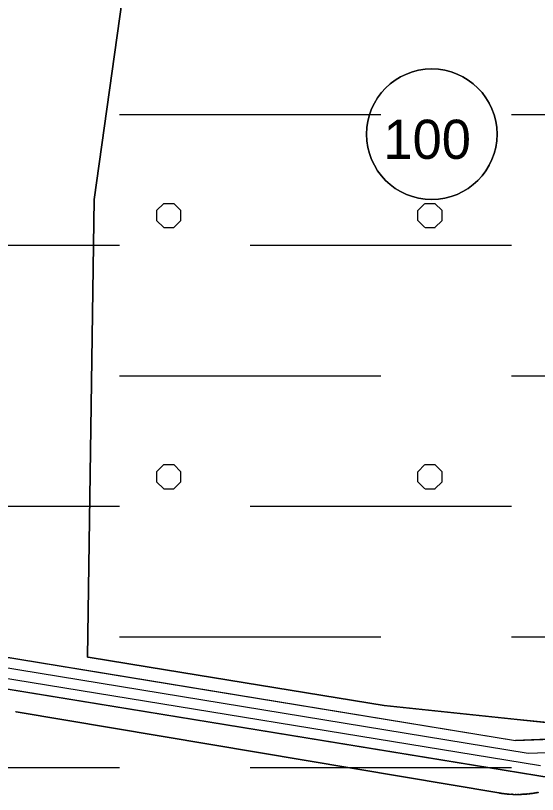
# Model space of a CAD drawing. Extents: x 409341 to 428634, y 4447481 to 4463281.
# Drawn here: x 419692.6 to 419892.4, y 4458246.6 to 4458544.8 of the extents above; entities that cross this region are included whole.
import ezdxf

# ---------------------------------------------------------------- set-up
doc = ezdxf.new("R2010")
doc.units = 0
for name, color, linetype in [('ADAKENARI', 7, 'Continuous'), ('KALDIRIM', 7, 'Continuous'), ('PL_KA_TARIM_ALANI', 7, 'Continuous'), ('PL_KON_ONE_100', 7, 'Continuous'), ('SM_DAIRE', 7, 'Continuous'), ('SM_TAKS', 7, 'Continuous'), ('SN_TR_TASKIN', 7, 'Continuous'), ('TR_AZGELISME', 7, 'Continuous'), ('TR_TARIMALANI', 7, 'Continuous')]:
    doc.layers.add(name, color=color, linetype=linetype)

msp = doc.modelspace()

# ---------------------------------------------------------------- linework, layer by layer
at = {"layer": 'ADAKENARI'}
for p, q in [((419722.68, 4458474.32), (419720.19, 4458299.14)), ((419673.34, 4458301.74), (419884.01, 4458267.29)), ((419671.41, 4458289.89), (419898.39, 4458252.78)), ((419833.71, 4458280.58), (419884.64, 4458275.31)), ((419884.64, 4458275.31), (419906.29, 4458273.07)), ((419955.41, 4458269.77), (419884.01, 4458267.29))]:
    msp.add_line(p, q, dxfattribs=at)
for points in [[(419783, 4458743.98), (419782.81, 4458726.4), (419748.11, 4458655.62), (419722.68, 4458474.32)], [(419720.19, 4458299.14), (419721.17, 4458298.98), (419750.03, 4458294.26), (419833.71, 4458280.58)]]:
    msp.add_lwpolyline(points, dxfattribs=at)
at = {"layer": 'KALDIRIM'}
for p, q in [((419672.7, 4458297.79), (419888.8, 4458262.45)), ((419672.05, 4458293.84), (419893.6, 4458257.62)), ((419888.8, 4458262.45), (419955.19, 4458264.76))]:
    msp.add_line(p, q, dxfattribs=at)
at = {"layer": 'PL_KA_TARIM_ALANI'}
for p, q in [((419692.64, 4458278.3), (419692.55, 4458278.32)), ((419878.14, 4458247.09), (419878.03, 4458247.11)), ((419891.85, 4458247.23), (419891.74, 4458247.22)), ((419881.06, 4458246.75), (419880.95, 4458246.75)), ((419881.28, 4458246.73), (419881.17, 4458246.74)), ((419882.48, 4458246.65), (419882.37, 4458246.66)), ((419882.8, 4458246.64), (419882.69, 4458246.64)), ((419883.24, 4458246.62), (419883.13, 4458246.62)), ((419883.79, 4458246.61), (419883.68, 4458246.61)), ((419886.85, 4458246.66), (419886.75, 4458246.65)), ((419888.49, 4458246.78), (419888.38, 4458246.77)), ((419888.82, 4458246.81), (419888.71, 4458246.8)), ((419889.36, 4458246.87), (419889.25, 4458246.86))]:
    msp.add_line(p, q, dxfattribs=at)
for points in [[(419673.34, 4458301.74), (419884.01, 4458267.29), (419932.9, 4458268.99), (419933.38, 4458274.01), (419913.55, 4458273.32), (419906.29, 4458273.07), (419884.64, 4458275.31), (419833.71, 4458280.58), (419750.03, 4458294.26), (419721.17, 4458298.98), (419720.19, 4458299.14), (419722.68, 4458474.32), (419748.11, 4458655.62), (419782.81, 4458726.4), (419783, 4458743.98), (419717.61, 4458711.06)], [(419930.98, 4458248.91), (419931.46, 4458253.93), (419898.39, 4458252.78), (419671.41, 4458289.89)], [(419692.55, 4458278.32), (419692.64, 4458278.3), (419692.73, 4458278.29), (419692.82, 4458278.27), (419692.92, 4458278.26), (419692.92, 4458278.26), (419877.6, 4458247.18), (419877.6, 4458247.18), (419877.71, 4458247.16), (419877.81, 4458247.15), (419877.92, 4458247.13), (419878.03, 4458247.11), (419878.14, 4458247.09), (419878.24, 4458247.08), (419878.35, 4458247.06), (419878.46, 4458247.05), (419878.57, 4458247.03), (419878.67, 4458247.01), (419878.78, 4458247), (419878.89, 4458246.98), (419879, 4458246.97), (419879.11, 4458246.96), (419879.21, 4458246.94), (419879.32, 4458246.93), (419879.43, 4458246.91), (419879.54, 4458246.9), (419879.65, 4458246.89), (419879.75, 4458246.88), (419879.86, 4458246.86), (419879.97, 4458246.85), (419880.08, 4458246.84), (419880.19, 4458246.83), (419880.3, 4458246.82), (419880.41, 4458246.81), (419880.51, 4458246.79), (419880.62, 4458246.78), (419880.73, 4458246.77), (419880.84, 4458246.76), (419880.95, 4458246.75), (419881.06, 4458246.75), (419881.17, 4458246.74), (419881.28, 4458246.73), (419881.38, 4458246.72), (419881.49, 4458246.71), (419881.6, 4458246.7), (419881.71, 4458246.7), (419881.82, 4458246.69), (419881.93, 4458246.68), (419882.04, 4458246.67), (419882.15, 4458246.67), (419882.26, 4458246.66), (419882.37, 4458246.66), (419882.48, 4458246.65), (419882.58, 4458246.65), (419882.69, 4458246.64), (419882.8, 4458246.64), (419882.91, 4458246.63), (419883.02, 4458246.63), (419883.13, 4458246.62), (419883.24, 4458246.62), (419883.35, 4458246.62), (419883.46, 4458246.61), (419883.57, 4458246.61), (419883.68, 4458246.61), (419883.79, 4458246.61), (419883.9, 4458246.6), (419884.01, 4458246.6), (419884.12, 4458246.6), (419884.23, 4458246.6), (419884.34, 4458246.6), (419884.45, 4458246.6), (419884.55, 4458246.6), (419884.66, 4458246.6), (419884.77, 4458246.6), (419884.88, 4458246.6), (419884.99, 4458246.6), (419885.1, 4458246.6), (419885.21, 4458246.6), (419885.32, 4458246.61), (419885.43, 4458246.61), (419885.54, 4458246.61), (419885.65, 4458246.61), (419885.76, 4458246.62), (419885.87, 4458246.62), (419885.98, 4458246.62), (419886.09, 4458246.63), (419886.2, 4458246.63), (419886.31, 4458246.63), (419886.42, 4458246.64), (419886.53, 4458246.64), (419886.64, 4458246.65), (419886.75, 4458246.65), (419886.85, 4458246.66), (419886.96, 4458246.67), (419887.07, 4458246.67), (419887.18, 4458246.68), (419887.29, 4458246.69), (419887.4, 4458246.69), (419887.51, 4458246.7), (419887.62, 4458246.71), (419887.73, 4458246.72), (419887.84, 4458246.73), (419887.95, 4458246.73), (419888.06, 4458246.74), (419888.17, 4458246.75), (419888.27, 4458246.76), (419888.38, 4458246.77), (419888.49, 4458246.78), (419888.6, 4458246.79), (419888.71, 4458246.8), (419888.82, 4458246.81), (419888.93, 4458246.83), (419889.04, 4458246.84), (419889.15, 4458246.85), (419889.25, 4458246.86), (419889.36, 4458246.87), (419889.47, 4458246.89), (419889.58, 4458246.9), (419889.69, 4458246.91), (419889.8, 4458246.93), (419889.91, 4458246.94), (419890.01, 4458246.95), (419890.12, 4458246.97), (419890.23, 4458246.98), (419890.34, 4458247), (419890.45, 4458247.01), (419890.56, 4458247.03), (419890.66, 4458247.04), (419890.77, 4458247.06), (419890.88, 4458247.08), (419890.99, 4458247.09), (419891.09, 4458247.11), (419891.2, 4458247.13), (419891.31, 4458247.14), (419891.42, 4458247.16), (419891.53, 4458247.18), (419891.63, 4458247.2), (419891.74, 4458247.22), (419891.85, 4458247.23), (419891.96, 4458247.25), (419892.06, 4458247.27), (419892.17, 4458247.29), (419892.28, 4458247.31), (419892.38, 4458247.33), (419892.49, 4458247.35)], [(419877.71, 4458247.16), (419877.6, 4458247.18), (419692.92, 4458278.26)], [(419878.67, 4458247.01), (419878.57, 4458247.03), (419878.46, 4458247.05), (419878.35, 4458247.06), (419878.24, 4458247.08)], [(419891.09, 4458247.11), (419890.99, 4458247.09), (419890.88, 4458247.08)], [(419891.53, 4458247.18), (419891.42, 4458247.16), (419891.31, 4458247.14)], [(419892.38, 4458247.33), (419892.28, 4458247.31), (419892.17, 4458247.29)], [(419879.43, 4458246.91), (419879.32, 4458246.93), (419879.21, 4458246.94), (419879.11, 4458246.96), (419879, 4458246.97)], [(419879.97, 4458246.85), (419879.86, 4458246.86), (419879.75, 4458246.88)], [(419880.51, 4458246.79), (419880.41, 4458246.81), (419880.3, 4458246.82), (419880.19, 4458246.83)], [(419880.84, 4458246.76), (419880.73, 4458246.77), (419880.62, 4458246.78)], [(419881.6, 4458246.7), (419881.49, 4458246.71), (419881.38, 4458246.72)], [(419884.23, 4458246.6), (419884.12, 4458246.6), (419884.01, 4458246.6), (419883.9, 4458246.6)], [(419885.32, 4458246.61), (419885.21, 4458246.6), (419885.1, 4458246.6), (419884.99, 4458246.6), (419884.88, 4458246.6), (419884.77, 4458246.6)], [(419885.87, 4458246.62), (419885.76, 4458246.62), (419885.65, 4458246.61)], [(419886.2, 4458246.63), (419886.09, 4458246.63), (419885.98, 4458246.62)], [(419886.64, 4458246.65), (419886.53, 4458246.64), (419886.42, 4458246.64)], [(419887.73, 4458246.72), (419887.62, 4458246.71), (419887.51, 4458246.7), (419887.4, 4458246.69), (419887.29, 4458246.69), (419887.18, 4458246.68), (419887.07, 4458246.67), (419886.96, 4458246.67)], [(419888.06, 4458246.74), (419887.95, 4458246.73), (419887.84, 4458246.73)], [(419889.69, 4458246.91), (419889.58, 4458246.9), (419889.47, 4458246.89)], [(419890.45, 4458247.01), (419890.34, 4458247), (419890.23, 4458246.98), (419890.12, 4458246.97), (419890.01, 4458246.95)]]:
    msp.add_lwpolyline(points, dxfattribs=at)
for centre, radius, start, end in [((419708.02, 4458368), 91, 260.2742, 260.4484), ((419884.57, 4458288.6), 42, 260.5964, 261.0409), ((419884.57, 4458288.6), 42, 261.1892, 261.3374), ((419884.57, 4458288.6), 42, 278.0439, 278.6396), ((419884.57, 4458288.6), 42, 278.9374, 279.235), ((419884.57, 4458288.6), 42, 279.5326, 279.83), ((419884.57, 4458288.6), 42, 279.9787, 280.4245), ((419884.57, 4458288.6), 42, 280.7216, 281.4638), ((419884.57, 4458288.6), 42, 261.9308, 262.3762), ((419884.57, 4458288.6), 42, 262.9705, 263.4166), ((419884.57, 4458288.6), 42, 263.7141, 264.0116), ((419884.57, 4458288.6), 42, 264.4582, 264.6071), ((419884.57, 4458288.6), 42, 264.905, 265.054), ((419884.57, 4458288.6), 42, 265.203, 265.352), ((419884.57, 4458288.6), 42, 265.5011, 265.6501), ((419884.57, 4458288.6), 42, 265.9483, 266.9925), ((419884.57, 4458288.6), 42, 267.1418, 267.4403), ((419884.57, 4458288.6), 42, 267.5896, 268.0375), ((419884.57, 4458288.6), 42, 268.1869, 268.7843), ((419884.57, 4458288.6), 42, 268.9337, 269.0831), ((419884.57, 4458288.6), 42, 269.5313, 270.2785), ((419884.57, 4458288.6), 42, 271.0258, 271.4742), ((419884.57, 4458288.6), 42, 271.7731, 271.9226), ((419884.57, 4458288.6), 42, 272.2215, 272.5205), ((419884.57, 4458288.6), 42, 272.8194, 272.9688), ((419884.57, 4458288.6), 42, 273.1183, 273.2677), ((419884.57, 4458288.6), 42, 274.3136, 274.4629), ((419884.57, 4458288.6), 42, 274.7617, 275.2097), ((419884.57, 4458288.6), 42, 275.359, 275.6576), ((419884.57, 4458288.6), 42, 275.8068, 276.4038), ((419884.57, 4458288.6), 42, 276.553, 276.7021), ((419884.57, 4458288.6), 42, 277.0004, 277.4477)]:
    msp.add_arc(centre, radius, start, end, dxfattribs=at)
at = {"layer": 'PL_KON_ONE_100'}
msp.add_lwpolyline([(419748.11, 4458655.62), (419722.68, 4458474.32), (419720.19, 4458299.14), (419721.17, 4458298.98), (419750.03, 4458294.26), (419833.71, 4458280.58), (419884.64, 4458275.31), (419906.29, 4458273.07), (419913.55, 4458273.32), (419933.38, 4458274.01), (419944.04, 4458385.56), (419948.45, 4458431.71), (419949.34, 4458441.03), (419949.82, 4458445.99), (419950.92, 4458457.55), (419953.33, 4458545.33)], dxfattribs=at)
at = {"layer": 'SM_DAIRE'}
msp.add_circle((419851.95, 4458499.37), 25, dxfattribs=at)
at = {"layer": 'SN_TR_TASKIN'}
for p, q in [((419732.43, 4458506.9), (419832.43, 4458506.9)), ((419882.43, 4458506.9), (419982.43, 4458506.9)), ((419632.43, 4458456.9), (419732.43, 4458456.9)), ((419782.43, 4458456.9), (419882.43, 4458456.9)), ((419732.43, 4458406.9), (419832.43, 4458406.9)), ((419882.43, 4458406.9), (419921.23, 4458406.9)), ((419632.43, 4458356.9), (419732.43, 4458356.9)), ((419782.43, 4458356.9), (419882.43, 4458356.9)), ((419732.43, 4458306.9), (419832.43, 4458306.9)), ((419882.43, 4458306.9), (419909.87, 4458306.9)), ((419632.43, 4458256.9), (419732.43, 4458256.9)), ((419782.43, 4458256.9), (419819.82, 4458256.9)), ((419819.82, 4458256.9), (419882.43, 4458256.9))]:
    msp.add_line(p, q, dxfattribs=at)
at = {"layer": 'TR_AZGELISME'}
msp.add_lwpolyline([(419786.3, 4458745.65), (419783, 4458743.98), (419782.81, 4458726.4), (419748.11, 4458655.62), (419722.68, 4458474.32), (419720.19, 4458299.14), (419721.17, 4458298.98), (419750.03, 4458294.26), (419833.71, 4458280.58), (419884.64, 4458275.31), (419906.29, 4458273.07), (419913.55, 4458273.32), (419933.38, 4458274.01)], dxfattribs=at)
for start, end in [(0, 180), (180, 0)]:
    msp.add_arc((419851.95, 4458499.37), 25, start, end, dxfattribs=at)
at = {"layer": 'TR_TARIMALANI'}
for p, q in [((419746.64, 4458470.14), (419749.35, 4458472.85)), ((419749.37, 4458472.85), (419753.2, 4458472.85)), ((419755.89, 4458470.14), (419753.18, 4458472.85)), ((419846.64, 4458470.14), (419849.35, 4458472.85)), ((419849.37, 4458472.85), (419853.2, 4458472.85)), ((419855.89, 4458470.14), (419853.18, 4458472.85)), ((419746.66, 4458466.31), (419746.66, 4458470.14)), ((419755.91, 4458466.31), (419755.91, 4458470.14)), ((419846.66, 4458466.31), (419846.66, 4458470.14)), ((419855.91, 4458466.31), (419855.91, 4458470.14)), ((419749.35, 4458463.6), (419746.64, 4458466.31)), ((419753.18, 4458463.6), (419755.89, 4458466.31)), ((419849.35, 4458463.6), (419846.64, 4458466.31)), ((419853.18, 4458463.6), (419855.89, 4458466.31)), ((419749.37, 4458463.6), (419753.2, 4458463.6)), ((419849.37, 4458463.6), (419853.2, 4458463.6)), ((419746.64, 4458370.14), (419749.35, 4458372.85)), ((419749.37, 4458372.85), (419753.2, 4458372.85)), ((419755.89, 4458370.14), (419753.18, 4458372.85)), ((419846.64, 4458370.14), (419849.35, 4458372.85)), ((419849.37, 4458372.85), (419853.2, 4458372.85)), ((419855.89, 4458370.14), (419853.18, 4458372.85)), ((419746.66, 4458366.31), (419746.66, 4458370.14)), ((419755.91, 4458366.31), (419755.91, 4458370.14)), ((419846.66, 4458366.31), (419846.66, 4458370.14)), ((419855.91, 4458366.31), (419855.91, 4458370.14)), ((419749.35, 4458363.6), (419746.64, 4458366.31)), ((419749.37, 4458363.6), (419753.2, 4458363.6)), ((419753.18, 4458363.6), (419755.89, 4458366.31)), ((419849.35, 4458363.6), (419846.64, 4458366.31)), ((419849.37, 4458363.6), (419853.2, 4458363.6)), ((419853.18, 4458363.6), (419855.89, 4458366.31))]:
    msp.add_line(p, q, dxfattribs=at)

# ---------------------------------------------------------------- texts
at = {"layer": 'SM_TAKS'}
msp.add_text('100', height=15, dxfattribs=at).set_placement((419833.46, 4458489.92))

doc.saveas('drawing.dxf')
